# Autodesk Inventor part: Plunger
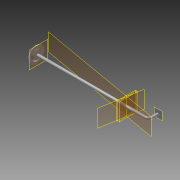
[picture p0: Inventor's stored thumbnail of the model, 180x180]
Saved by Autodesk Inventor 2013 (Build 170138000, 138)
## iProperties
Created: 2009-03
Part Number: Plunger
Document SubType Name: Modeling
Designer: tangg
Density: 8.03 g/cm^3
Material: Stainless Steel, Austenitic
Mass: 116.743 g
Surface Area: 101.946 cm^2
Volume: 14.5383 cm^3
Author: tangg
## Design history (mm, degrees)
sketch "Sketch1"
  geometry: L1 (0, 0)-(290, 0); L2 (300, 10)-(300, 25); A1 r 10 centre (290, 10) between (290, 0) and (300, 10); 1 further point
  constraints: 4 end point, 2 point on circle, 2 point on line, 2 tangent, 1 centre point, 1 horizontal, 1 perpendicular
  dimensions: "d0" = 300 distance of L1.start point (300, 0); "d1" = 25 distance of point (300, 0) L2.end; "d2" = 10 radius of A1
workplane "Work Plane1"
sketch "Sketch2"
  geometry: C1 r 3.5 at (0, 0); 3 further points
  constraints: 1 centre point, 1 coincident, 1 other
  dimensions: "d3" = 7 diameter of C1
sweep "Sweep1" sketch "Sketch2" dims "d4" = 0
sketch "Sketch3"
  geometry: L1 (-4.358, -21.225)-(-2.799, -21.225); L2 (-2.799, -21.225)-(-2.799, -15.815); L3 (-2.799, -15.815)-(-4.358, -15.815); L4 (-4.358, -15.815)-(-4.358, -21.225); L5 (0, 0)-(-1.559, 0); L6 (-1.559, 0)-(-1.559, -10.63); L7 (-1.559, -10.63)-(0, -10.63); L8 (0, -10.63)-(0, 0); L9 (-4.358, -15.815)-(-1.559, -10.63); L10 (-2.799, -15.815)-(0, -10.63)
  constraints: 20 end point, 5 parallel, 2 horizontal, 2 perpendicular
revolve "Revolution1" sketch "Sketch3" stored, may be unused: angle "d5" = 90 deg
chamfer "Chamfer1" distance "d6" = 1; stored, may be unused: second distance "d7" = 2, angle "d8" = 45 deg
workplane "Work Plane2"
workplane "Work Plane12"
workplane "Work Plane13"
workplane "Work Plane14"
workaxis "Work Axis2"
workplane "Work Plane16"
  workplane "Work Plane15"
split "Split7"
split "Split8"
split "Split9"
body "Solid1"
other parameters: "d18" = -3, "d19" = 3, "d20" = 10 deg, "d21" = 90 deg
